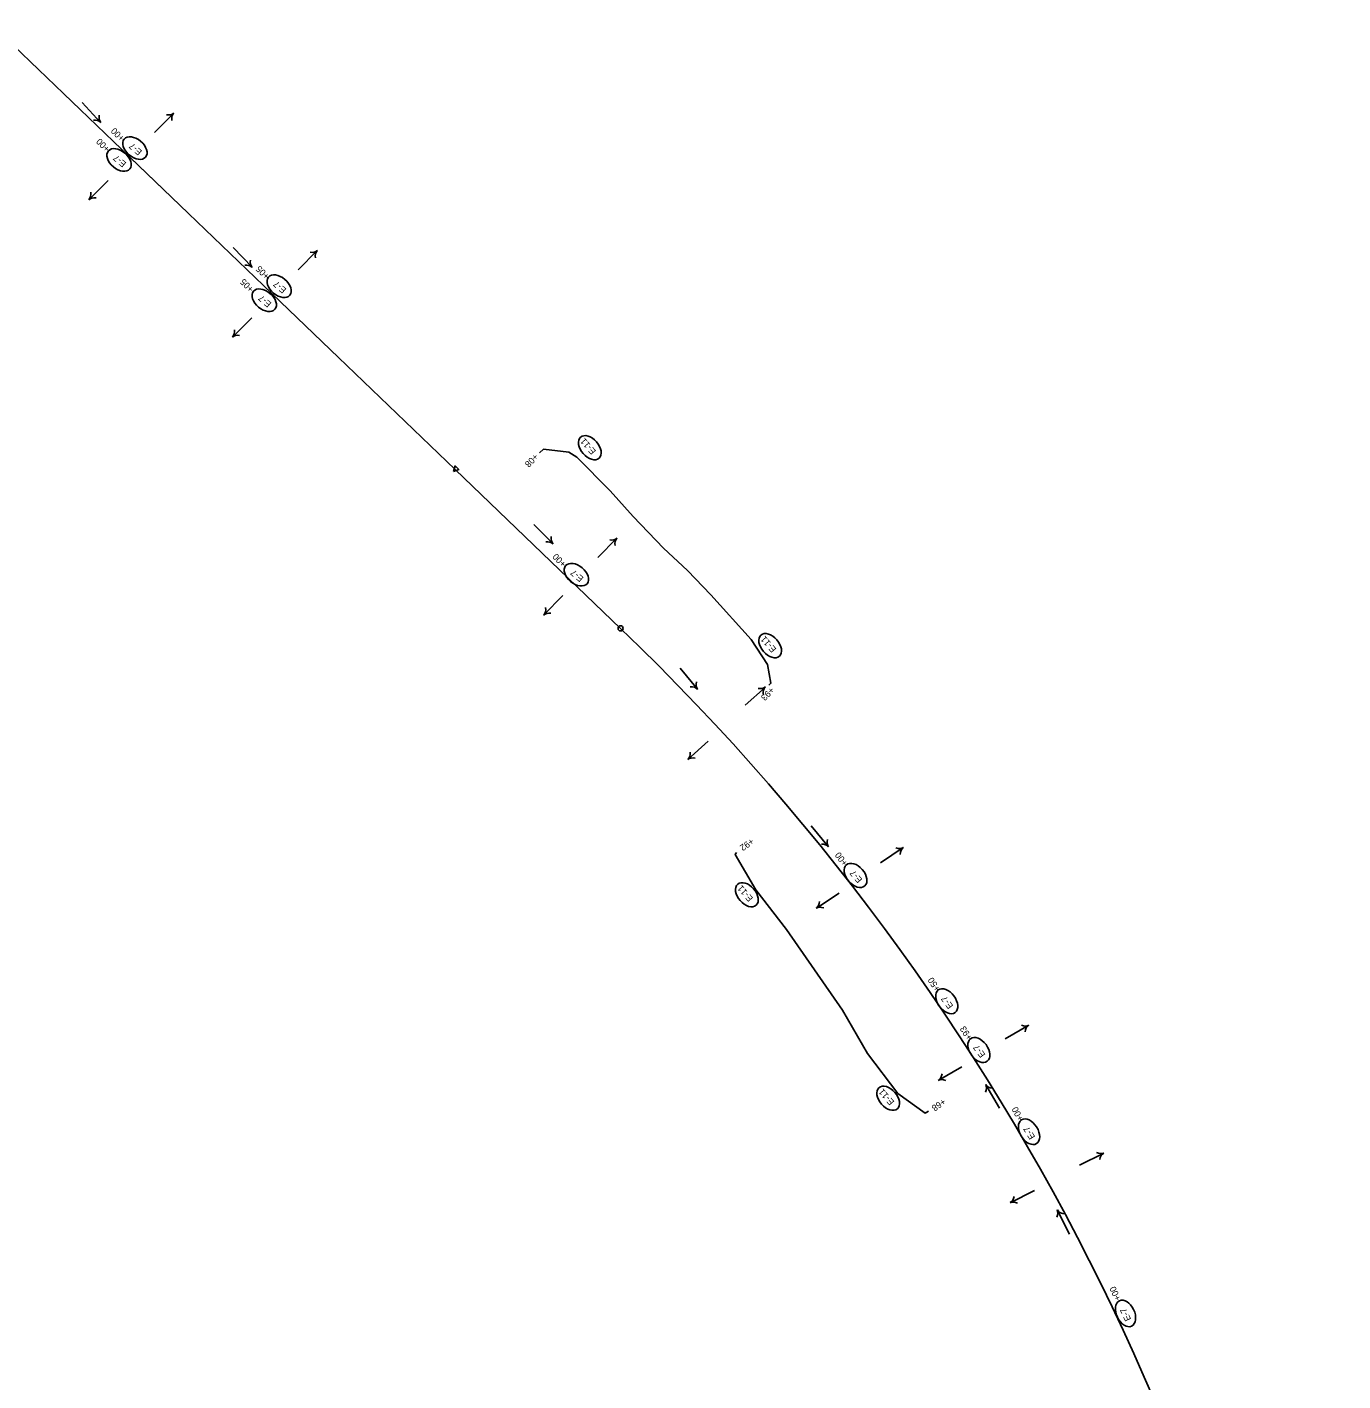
# Model space of a CAD drawing. Extents: x 669236 to 673912, y 735758 to 754788.
# Drawn here: x 672567 to 673851, y 750806 to 752127 of the extents above; entities that cross this region are included whole.
import ezdxf

# ---------------------------------------------------------------- set-up
doc = ezdxf.new("R2010")
doc.units = 0
for name, color, linetype in [('Default', 7, 'Continuous'), ('Prop_Horiz Alignment', 7, 'Continuous'), ('R_Erosion_2', 7, 'Continuous'), ('R_Erosion_3', 7, 'Continuous'), ('R_Flow Arrows', 7, 'Continuous')]:
    doc.layers.add(name, color=color, linetype=linetype)

msp = doc.modelspace()

# ---------------------------------------------------------------- linework, layer by layer
at = {"layer": 'Default'}
for p, q in [((672984.6, 751695), (671992.6, 752646.7)), ((673146.2, 751540.1), (672984.6, 751695))]:
    msp.add_line(p, q, dxfattribs=at)
msp.add_arc((671559.6, 749886.2), 2291.8, 325.1701, 46.1906, dxfattribs=at)
at = {"layer": 'Prop_Horiz Alignment'}
msp.add_lwpolyline([(672982.9, 751693.2), (672984.6, 751698.6), (672988.2, 751695.1)], close=True, dxfattribs=at)
msp.add_circle((673146.2, 751540.1), 2.5, dxfattribs=at)
at = {"layer": 'R_Erosion_2'}
msp.add_lwpolyline([(673291, 751484.7), (673293, 751486.6), (673289.7, 751504.8), (673273.5, 751529.1), (673234.2, 751572.8), (673211.6, 751596.7), (673188.1, 751618.5), (673158.6, 751649.3), (673135.9, 751674.3), (673103.5, 751707.3), (673095.7, 751712.2), (673071, 751715.1), (673067, 751711.4)], dxfattribs=at)
for centre, major_axis in [((672671.9, 752008.8), (-10.5, 8.8)), ((672656.5, 751997.2), (-10.5, 8.8)), ((672812.8, 751874), (-10.5, 8.8)), ((672798.2, 751860.3), (-10.5, 8.8)), ((673116.1, 751716.4), (-9, 10.3)), ((673103, 751592.5), (-10.5, 8.8)), ((673292.2, 751523.2), (-9, 10.3)), ((673375.6, 751299), (-9, 10.3)), ((673464.6, 751176.2), (-8.2, 11)), ((673496, 751128.6), (-8.2, 11)), ((673545, 751048.8), (-7.3, 11.6)), ((673639.2, 750871.5), (-5.9, 12.4))]:
    msp.add_ellipse(centre, major_axis=major_axis, ratio=0.638788, dxfattribs=at)
at = {"layer": 'R_Erosion_3'}
msp.add_lwpolyline([(673446.7, 751068.8), (673443.4, 751067), (673417, 751086.1), (673387.4, 751125.2), (673362.7, 751167.5), (673308.1, 751246.3), (673278.2, 751285), (673257.9, 751319.5), (673259.2, 751321.4)], dxfattribs=at)
for centre in [(673269.5, 751280.1), (673407.4, 751081.5)]:
    msp.add_ellipse(centre, major_axis=(-9, 10.3), ratio=0.638788, dxfattribs=at)
at = {"layer": 'R_Flow Arrows'}
for p, q in [((672638.5, 752033.9), (672620.3, 752053.3)), ((672709.8, 752042.8), (672691, 752024)), ((672627, 751958.4), (672645.8, 751977.2)), ((672786.3, 751892.6), (672767.8, 751911.7)), ((672850, 751908.7), (672831.2, 751889.9)), ((672767.2, 751824.3), (672786, 751843.1)), ((673080.3, 751622.7), (673061.3, 751641.3)), ((673142.6, 751628.1), (673123.8, 751609.3)), ((673071.2, 751553.3), (673089.9, 751572.1)), ((673221.2, 751480.6), (673204.2, 751501.1)), ((673287.5, 751482.8), (673267.7, 751465.1)), ((673211.9, 751412.2), (673231.7, 751429.9)), ((673349.1, 751327), (673332.3, 751347.5)), ((673422.2, 751326.1), (673400.1, 751311.4)), ((673337.3, 751267.1), (673359.5, 751281.7)), ((673544.7, 751152.7), (673521.7, 751139.5)), ((673456.4, 751099), (673479.4, 751112.3)), ((673502.7, 751094.7), (673516.2, 751071.9)), ((673617.9, 751028), (673594.2, 751016.1)), ((673526.5, 750979.6), (673550.3, 750991.5)), ((673572.5, 750972.6), (673584.6, 750948.9))]:
    msp.add_line(p, q, dxfattribs=at)
for centre, major_axis, start_param, end_param in [((672624, 752019.9), (14.7, 13.8), 0.023252, 0.620249), ((672653.5, 752047.4), (-14.7, -13.8), 5.662936, 6.259934), ((672695.8, 752057.4), (14.3, -14.2), 5.662936, 6.259934), ((672724.2, 752028.8), (-14.3, 14.2), 0.023252, 0.620249), ((672641, 751943.9), (-14.3, 14.2), 5.662936, 6.259934), ((672612.6, 751972.5), (14.3, -14.2), 0.023252, 0.620249), ((672836, 751923.3), (14.3, -14.2), 5.662936, 6.259934), ((672864.4, 751894.7), (-14.3, 14.2), 0.023252, 0.620249), ((672771.9, 751878.4), (14.5, 14), 0.023252, 0.620249), ((672801.1, 751906.2), (-14.5, -14), 5.662936, 6.259934), ((672781.2, 751809.8), (-14.3, 14.2), 5.662936, 6.259934), ((672752.8, 751838.4), (14.3, -14.2), 0.023252, 0.620249), ((673066.3, 751608.1), (14.1, 14.4), 0.023252, 0.620249), ((673094.7, 751636.8), (-14.1, -14.4), 5.662936, 6.259934), ((673128.6, 751642.6), (14.3, -14.2), 5.662936, 6.259934), ((673157, 751614), (-14.3, 14.2), 0.023252, 0.620249), ((673056.7, 751567.3), (14.3, -14.2), 0.023252, 0.620249), ((673085.1, 751538.7), (-14.3, 14.2), 5.662936, 6.259934), ((673205.8, 751467.6), (15.5, 12.9), 0.023252, 0.620249), ((673237, 751493.2), (-15.5, -12.9), 5.662936, 6.259934), ((673274.4, 751498.1), (13.4, -15), 5.662936, 6.259934), ((673301.1, 751467.9), (-13.4, 15), 0.023252, 0.620249), ((673225, 751396.9), (-13.4, 15), 5.662936, 6.259934), ((673198.3, 751427), (13.4, -15), 0.023252, 0.620249), ((673365, 751339.4), (-15.6, -12.8), 5.662936, 6.259934), ((673333.7, 751314), (15.6, 12.8), 0.023252, 0.620249), ((673411.5, 751343.2), (11.1, -16.8), 5.662936, 6.259934), ((673433.6, 751309.5), (-11.1, 16.8), 0.023252, 0.620249), ((673348.1, 751250), (-11.1, 16.8), 5.662936, 6.259934), ((673326, 751283.7), (11.1, -16.8), 0.023252, 0.620249), ((673535, 751170.4), (10.1, -17.5), 5.662936, 6.259934), ((673555, 751135.4), (-10.1, 17.5), 0.023252, 0.620249), ((673466.1, 751081.3), (-10.1, 17.5), 5.662936, 6.259934), ((673446.1, 751116.3), (10.1, -17.5), 0.023252, 0.620249), ((673485.1, 751084.9), (17.4, 10.2), 5.662936, 6.259934), ((673520, 751105.2), (-17.4, -10.2), 0.023252, 0.620249), ((673609.3, 751046.2), (9, -18), 5.662936, 6.259934), ((673627.2, 751010.1), (-9, 18), 0.023252, 0.620249), ((673535.2, 750961.4), (-9, 18), 5.662936, 6.259934), ((673517.3, 750997.5), (9, -18), 0.023252, 0.620249), ((673554.4, 750963.8), (17.9, 9.2), 5.662936, 6.259934), ((673590.4, 750982), (-17.9, -9.2), 0.023252, 0.620249)]:
    msp.add_ellipse(centre, major_axis=major_axis, ratio=0.5625, start_param=start_param, end_param=end_param, dxfattribs=at)

# ---------------------------------------------------------------- texts
at = {"layer": 'R_Erosion_2'}
for s, rotation, p in [('+00', 134.4293, (672662.3, 752019.1)), ('+00', 134.4293, (672647.9, 752008.7)), ('E-7', 139.7558, (672679.4, 752005.9)), ('E-7', 139.7558, (672664, 751994.3)), ('+05', 134.4293, (672803.8, 751884.4)), ('+05', 134.4293, (672788.4, 751871.8)), ('E-7', 139.7558, (672820.3, 751871.2)), ('E-7', 139.7558, (672805.7, 751857.5)), ('E-11', 130.9328, (673122.5, 751713.1)), ('+08', 225.7897, (673062, 751711.1)), ('+00', 134.4293, (673093.5, 751603.6)), ('E-7', 139.7558, (673110.5, 751589.6)), ('E-11', 130.9328, (673298.6, 751519.9)), ('+93', 225.7794, (673292.5, 751483.4)), ('+00', 126.2499, (673368.4, 751311)), ('E-7', 130.9257, (673382.6, 751295)), ('+50', 122.8392, (673458.6, 751188.3)), ('E-7', 126.7259, (673471.3, 751171.7)), ('+93', 122.8392, (673490, 751140.7)), ('E-7', 126.7259, (673502.7, 751124.1)), ('+00', 118.12, (673539.9, 751061.4)), ('E-7', 122.0067, (673551.2, 751043.8)), ('+00', 114.6432, (673634.9, 750885.7)), ('E-7', 115.4099, (673644.8, 750865.8))]:
    msp.add_text(s, height=6.25, rotation=rotation, dxfattribs=at).set_placement(p)
at = {"layer": 'R_Erosion_3'}
for s, rotation, p in [('+92', 215, (673273.6, 751335.7)), ('E-11', 130.9328, (673275.9, 751276.8)), ('E-11', 130.9328, (673413.8, 751078.1)), ('+68', 215, (673460.9, 751081.6))]:
    msp.add_text(s, height=6.25, rotation=rotation, dxfattribs=at).set_placement(p)

doc.saveas('drawing.dxf')
